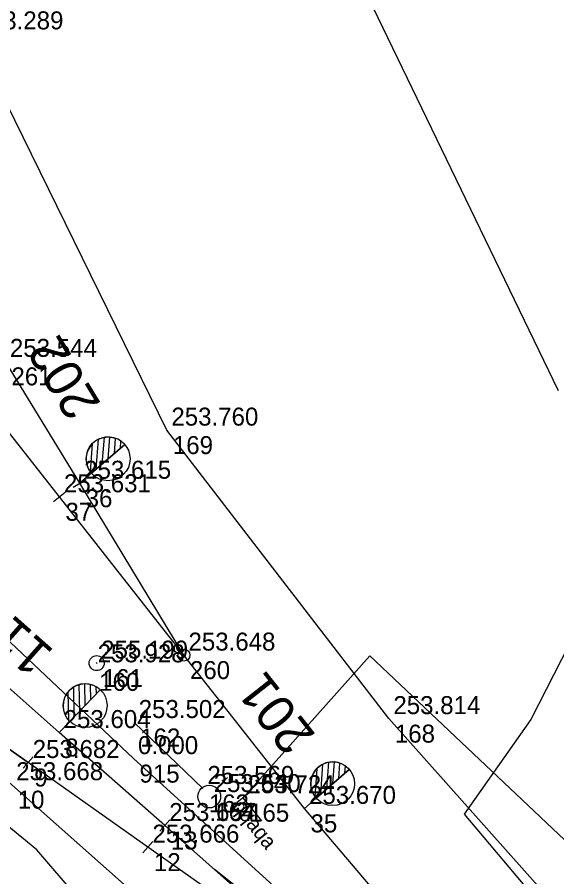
# Model space of a CAD drawing. Extents: x -496688 to -495455, y -1089309 to -1088026.
# Drawn here: x -495862.8 to -495826.8, y -1088721 to -1088663.7 of the extents above; entities that cross this region are included whole.
import ezdxf

# ---------------------------------------------------------------- set-up
doc = ezdxf.new("R2010")
doc.units = 0
for name, color, linetype in [('Vrstva 1', 7, 'Continuous'), ('Vrstva 2', 7, 'Continuous'), ('Vrstva 25', 7, 'Continuous'), ('Vrstva 36', 7, 'Continuous'), ('Vrstva 49', 7, 'Continuous'), ('Vrstva 53', 7, 'Continuous'), ('Vrstva 55', 7, 'Continuous'), ('Vrstva 6', 7, 'Continuous'), ('Vrstva 60', 7, 'Continuous'), ('Vrstva 61', 7, 'Continuous')]:
    doc.layers.add(name, color=color, linetype=linetype)

msp = doc.modelspace()

# ---------------------------------------------------------------- linework, layer by layer
at = {"layer": 'Vrstva 1'}
for points in [[(-495794.281, -1088769.662), (-495806.718, -1088758.644), (-495819.114, -1088747.662), (-495828.107, -1088739.648), (-495840.608, -1088728.579), (-495852.984, -1088717.621), (-495860.029, -1088711.42), (-495872.461, -1088700.397), (-495884.955, -1088689.319), (-495893.533, -1088681.721), (-495913.179, -1088664.263), (-495947.105, -1088634.191), (-495952.116, -1088629.76), (-495964.613, -1088618.686), (-495984.901, -1088600.717), (-495997.336, -1088589.715), (-496002.819, -1088584.884), (-496021.751, -1088568.167), (-496024.418, -1088565.811), (-496062.504, -1088532.205), (-496086.773, -1088510.767), (-496106.199, -1088493.629), (-496127.249, -1088474.987), (-496164.633, -1088441.927)], [(-495860.009, -1088695.696), (-495879.111, -1088671.4), (-495889.727, -1088657.952), (-495895.948, -1088650.027), (-495908.172, -1088634.454), (-495920.247, -1088619.061), (-495928.37, -1088608.7), (-495943.31, -1088589.65), (-495946.89, -1088584.98), (-495957.87, -1088569.42), (-495971.21, -1088547.86), (-495978.61, -1088535.04), (-495988.2, -1088517.33), (-495993.92, -1088506.2), (-495995.29, -1088503.47), (-496002.91, -1088487.94)], [(-495784.233, -1088784.889), (-495790.007, -1088779.778), (-495797.538, -1088773.109), (-495802.96, -1088768.305), (-495829.435, -1088744.846), (-495841.88, -1088733.81), (-495854.312, -1088722.787), (-495863.196, -1088714.897), (-495875.701, -1088703.825), (-495888.14, -1088692.81), (-495895.834, -1088685.958), (-495903.705, -1088678.98), (-495916.136, -1088667.962), (-495923.285, -1088661.656)], [(-495851.703, -1088706.254), (-495858.66, -1088694.79), (-495863.612, -1088686.663), (-495872.713, -1088671.728)], [(-495843.661, -1088716.477), (-495851.703, -1088706.254), (-495860.009, -1088695.696)], [(-495597.746, -1088928.689), (-495606.602, -1088921.27), (-495628.038, -1088903.237), (-495662.023, -1088874.554), (-495695.238, -1088846.561), (-495728.41, -1088818.593), (-495747.734, -1088802.274), (-495769.843, -1088783.642), (-495779.5, -1088775.496), (-495789.139, -1088767.364), (-495796.782, -1088760.905), (-495804.819, -1088754.113), (-495818.323, -1088744.415), (-495826.921, -1088738.229), (-495840.608, -1088728.579), (-495854.107, -1088719.062), (-495862.093, -1088713.418), (-495875.701, -1088703.825)], [(-495817.188, -1088742.979), (-495827.498, -1088733.605), (-495838.015, -1088723.129), (-495843.661, -1088716.477)]]:
    msp.add_lwpolyline(points, dxfattribs=at)
at = {"layer": 'Vrstva 2'}
for p, q in [((-495857.944, -1088694.031), (-495857.799, -1088692.138)), ((-495857.554, -1088693.846), (-495857.401, -1088691.854)), ((-495857.152, -1088693.501), (-495857.015, -1088691.73)), ((-495856.75, -1088693.154), (-495856.639, -1088691.714)), ((-495856.347, -1088692.81), (-495856.269, -1088691.798)), ((-495855.944, -1088692.464), (-495855.907, -1088691.989)), ((-495857.877, -1088694.123), (-495855.655, -1088692.217)), ((-495855.655, -1088692.217), (-495857.877, -1088694.122)), ((-495857.878, -1088694.123), (-495858.66, -1088694.79)), ((-495857.877, -1088694.122), (-495857.877, -1088694.123)), ((-495859.087, -1088695.049), (-495858.233, -1088694.531)), ((-495860.401, -1088696.005), (-495859.617, -1088695.387)), ((-495858.283, -1088709.609), (-495858.311, -1088708.166)), ((-495859.389, -1088710.596), (-495859.426, -1088708.698)), ((-495859.314, -1088710.681), (-495857.285, -1088708.571)), ((-495857.285, -1088708.571), (-495859.314, -1088710.68)), ((-495859.019, -1088710.375), (-495859.057, -1088708.377)), ((-495858.651, -1088709.993), (-495858.686, -1088708.217)), ((-495857.916, -1088709.227), (-495857.936, -1088708.212)), ((-495857.548, -1088708.845), (-495857.557, -1088708.368)), ((-495859.314, -1088710.682), (-495860.029, -1088711.42)), ((-495859.314, -1088710.68), (-495859.314, -1088710.681)), ((-495862.424, -1088713.792), (-495861.762, -1088713.044)), ((-495842.953, -1088715.712), (-495842.827, -1088713.818)), ((-495840.682, -1088713.874), (-495842.885, -1088715.801)), ((-495842.884, -1088715.802), (-495840.682, -1088713.874)), ((-495842.564, -1088715.523), (-495842.431, -1088713.528)), ((-495842.166, -1088715.173), (-495842.047, -1088713.401)), ((-495841.767, -1088714.823), (-495841.67, -1088713.383)), ((-495841.367, -1088714.474), (-495841.299, -1088713.461)), ((-495840.968, -1088714.124), (-495840.935, -1088713.649)), ((-495842.885, -1088715.802), (-495843.661, -1088716.477)), ((-495842.885, -1088715.801), (-495842.884, -1088715.802)), ((-495853.316, -1088717.995), (-495852.652, -1088717.247)), ((-495854.439, -1088719.436), (-495853.775, -1088718.688))]:
    msp.add_line(p, q, dxfattribs=at)
for points in [[(-495858.66, -1088694.79), (-495863.612, -1088686.663), (-495872.713, -1088671.728)], [(-495860.029, -1088711.42), (-495872.461, -1088700.397), (-495884.955, -1088689.319)], [(-495851.703, -1088706.254), (-495858.66, -1088694.79)], [(-495843.661, -1088716.477), (-495851.703, -1088706.254), (-495860.009, -1088695.696)], [(-495875.701, -1088703.825), (-495862.093, -1088713.418)], [(-495828.107, -1088739.648), (-495840.608, -1088728.579), (-495852.983, -1088717.62)], [(-495826.921, -1088738.229), (-495840.608, -1088728.579), (-495854.107, -1088719.062)], [(-495830.797, -1088735.496), (-495849.674, -1088720.551)]]:
    msp.add_lwpolyline(points, dxfattribs=at)
for centre, radius in [((-495856.761, -1088693.163), 1.462), ((-495851.703, -1088706.254), 0.4), ((-495858.294, -1088709.619), 1.462), ((-495841.778, -1088714.832), 1.462)]:
    msp.add_circle(centre, radius, dxfattribs=at)
for centre, start, end in [((-495856.766, -1088693.17), 40.62641, 220.58726), ((-495858.299, -1088709.626), 46.11677, 226.07762), ((-495841.783, -1088714.838), 41.1877, 221.14855)]:
    msp.add_arc(centre, 1.464, start, end, dxfattribs=at)
at = {"layer": 'Vrstva 25'}
msp.add_line((-495857.489, -1088706.822), (-495857.563, -1088706.756), dxfattribs=at)
msp.add_circle((-495857.526, -1088706.789), 0.5, dxfattribs=at)
at = {"layer": 'Vrstva 36'}
msp.add_line((-495849.493, -1088715.144), (-495848.802, -1088714.421), dxfattribs=at)
msp.add_lwpolyline([(-495850.441, -1088715.147), (-495855.024, -1088710.75)], dxfattribs=at)
msp.add_circle((-495850.017, -1088715.689), 0.757, dxfattribs=at)
at = {"layer": 'Vrstva 49'}
msp.add_lwpolyline([(-495763.13, -1088778.611), (-495765.306, -1088777.077), (-495791.441, -1088755.289), (-495814.323, -1088737.085), (-495838.033, -1088710.491), (-495852.843, -1088691.248), (-495865.843, -1088664.821), (-495876.068, -1088642.052), (-495881.546, -1088626.667), (-495882.811, -1088621.688)], dxfattribs=at)
at = {"layer": 'Vrstva 53'}
for p, q in [((-495859.86, -1088620.14), (-495826.74, -1088688.6)), ((-495825.16, -1088703.86), (-495828.57, -1088710.55)), ((-495828.57, -1088710.55), (-495833.01, -1088716.87)), ((-495833.01, -1088716.87), (-495825.11, -1088726.21))]:
    msp.add_line(p, q, dxfattribs=at)
at = {"layer": 'Vrstva 55'}
for p, q in [((-495861.51, -1088719.25), (-495872.18, -1088710.53)), ((-495820.95, -1088766.37), (-495861.51, -1088719.25))]:
    msp.add_line(p, q, dxfattribs=at)
msp.add_lwpolyline([(-495876.99, -1088692.49), (-495855.07, -1088713.16), (-495793.54, -1088769.11), (-495671.98, -1088874.82), (-495634.71, -1088905.31), (-495611.24, -1088924.48), (-495609.02, -1088926.3), (-495602.5, -1088931.63)], dxfattribs=at)
at = {"layer": 'Vrstva 6'}
for p, q in [((-495847.758, -1088715.765), (-495839.294, -1088706.307)), ((-495839.294, -1088706.307), (-495815.484, -1088728.83)), ((-495847.368, -1088715.452), (-495848.148, -1088716.078)), ((-495846.519, -1088717.311), (-495847.758, -1088715.765))]:
    msp.add_line(p, q, dxfattribs=at)
at = {"layer": 'Vrstva 60'}
for p, q in [((-495852.843, -1088691.248), (-495852.843, -1088691.248)), ((-495852.843, -1088691.248), (-495852.843, -1088691.248)), ((-495858.66, -1088694.79), (-495858.66, -1088694.79)), ((-495858.66, -1088694.79), (-495858.66, -1088694.79)), ((-495860.009, -1088695.696), (-495860.009, -1088695.696)), ((-495860.009, -1088695.696), (-495860.009, -1088695.696)), ((-495851.703, -1088706.254), (-495851.703, -1088706.254)), ((-495851.703, -1088706.254), (-495851.703, -1088706.254)), ((-495857.759, -1088707.036), (-495857.759, -1088707.036)), ((-495857.759, -1088707.036), (-495857.759, -1088707.036)), ((-495857.526, -1088706.789), (-495857.526, -1088706.789)), ((-495857.526, -1088706.789), (-495857.526, -1088706.789)), ((-495855.024, -1088710.75), (-495855.024, -1088710.75)), ((-495855.024, -1088710.75), (-495855.024, -1088710.75)), ((-495838.033, -1088710.491), (-495838.033, -1088710.491)), ((-495838.033, -1088710.491), (-495838.033, -1088710.491)), ((-495860.029, -1088711.42), (-495860.029, -1088711.42)), ((-495860.029, -1088711.42), (-495860.029, -1088711.42)), ((-495855.07, -1088713.16), (-495855.07, -1088713.16)), ((-495855.07, -1088713.16), (-495855.07, -1088713.16)), ((-495862.093, -1088713.418), (-495862.093, -1088713.418)), ((-495862.093, -1088713.418), (-495862.093, -1088713.418)), ((-495850.441, -1088715.147), (-495850.441, -1088715.147)), ((-495850.441, -1088715.147), (-495850.441, -1088715.147)), ((-495850.017, -1088715.69), (-495850.017, -1088715.69)), ((-495850.017, -1088715.69), (-495850.017, -1088715.69)), ((-495847.758, -1088715.765), (-495847.758, -1088715.765)), ((-495847.758, -1088715.765), (-495847.758, -1088715.765)), ((-495843.661, -1088716.477), (-495843.661, -1088716.477)), ((-495843.661, -1088716.477), (-495843.661, -1088716.477)), ((-495852.984, -1088717.621), (-495852.984, -1088717.621)), ((-495852.984, -1088717.621), (-495852.984, -1088717.621)), ((-495854.107, -1088719.062), (-495854.107, -1088719.062)), ((-495854.107, -1088719.062), (-495854.107, -1088719.062))]:
    msp.add_line(p, q, dxfattribs=at)

# ---------------------------------------------------------------- texts
at = {"layer": 'Vrstva 2'}
for s, rotation, p in [('202', 121.25175, (-495857.206, -1088689.502)), ('11', 138.39129, (-495860.293, -1088705.999)), ('201', 128.19063, (-495842.868, -1088711.586))]:
    msp.add_text(s, height=2.5, rotation=rotation, dxfattribs=at).set_placement(p)
at = {"layer": 'Vrstva 6'}
msp.add_text('qqaqa', height=1, rotation=308.70973, dxfattribs=at).set_placement((-495848.538, -1088716.39))
at = {"layer": 'Vrstva 60'}
for s, p in [('261', (-495863.212, -1088688.263)), ('261', (-495863.212, -1088688.263)), ('169', (-495852.443, -1088692.848)), ('169', (-495852.443, -1088692.848)), ('36', (-495858.26, -1088696.39)), ('36', (-495858.26, -1088696.39)), ('37', (-495859.609, -1088697.296)), ('37', (-495859.609, -1088697.296)), ('260', (-495851.303, -1088707.854)), ('260', (-495851.303, -1088707.854)), ('160', (-495857.359, -1088708.636)), ('160', (-495857.359, -1088708.636)), ('161', (-495857.126, -1088708.389)), ('161', (-495857.126, -1088708.389)), ('168', (-495837.633, -1088712.091)), ('168', (-495837.633, -1088712.091)), ('162', (-495854.624, -1088712.35)), ('162', (-495854.624, -1088712.35)), ('8', (-495859.629, -1088713.02)), ('8', (-495859.629, -1088713.02)), ('9', (-495861.693, -1088715.018)), ('9', (-495861.693, -1088715.018)), ('915', (-495854.67, -1088714.76)), ('915', (-495854.67, -1088714.76)), ('10', (-495862.796, -1088716.497)), ('10', (-495862.796, -1088716.497)), ('163', (-495850.041, -1088716.747)), ('163', (-495850.041, -1088716.747)), ('164', (-495849.617, -1088717.29)), ('164', (-495849.617, -1088717.29)), ('165', (-495847.358, -1088717.365)), ('165', (-495847.358, -1088717.365)), ('35', (-495843.261, -1088718.077)), ('35', (-495843.261, -1088718.077)), ('13', (-495852.584, -1088719.221)), ('13', (-495852.584, -1088719.221)), ('12', (-495853.707, -1088720.662)), ('12', (-495853.707, -1088720.662))]:
    msp.add_text(s, height=1.2, dxfattribs=at).set_placement(p)
at = {"layer": 'Vrstva 61'}
for s, p in [('253.289', (-495865.543, -1088664.521)), ('253.289', (-495865.543, -1088664.521)), ('253.544', (-495863.312, -1088686.363)), ('253.544', (-495863.312, -1088686.363)), ('253.760', (-495852.543, -1088690.948)), ('253.760', (-495852.543, -1088690.948)), ('253.615', (-495858.36, -1088694.49)), ('253.615', (-495858.36, -1088694.49)), ('253.631', (-495859.709, -1088695.396)), ('253.631', (-495859.709, -1088695.396)), ('253.648', (-495851.403, -1088705.954)), ('253.648', (-495851.403, -1088705.954)), ('255.199', (-495857.226, -1088706.489)), ('255.199', (-495857.226, -1088706.489)), ('253.928', (-495857.459, -1088706.736)), ('253.928', (-495857.459, -1088706.736)), ('253.502', (-495854.724, -1088710.45)), ('253.502', (-495854.724, -1088710.45)), ('253.814', (-495837.733, -1088710.191)), ('253.814', (-495837.733, -1088710.191)), ('253.604', (-495859.729, -1088711.12)), ('253.604', (-495859.729, -1088711.12)), ('253.682', (-495861.793, -1088713.118)), ('253.682', (-495861.793, -1088713.118)), ('0.000', (-495854.77, -1088712.86)), ('0.000', (-495854.77, -1088712.86)), ('253.668', (-495862.896, -1088714.597)), ('253.668', (-495862.896, -1088714.597)), ('253.569', (-495850.141, -1088714.847)), ('253.569', (-495850.141, -1088714.847)), ('253.640', (-495849.717, -1088715.39)), ('253.640', (-495849.717, -1088715.39)), ('253.724', (-495847.458, -1088715.465)), ('253.724', (-495847.458, -1088715.465)), ('253.670', (-495843.361, -1088716.177)), ('253.670', (-495843.361, -1088716.177)), ('253.657', (-495852.684, -1088717.321)), ('253.657', (-495852.684, -1088717.321)), ('253.666', (-495853.807, -1088718.762)), ('253.666', (-495853.807, -1088718.762))]:
    msp.add_text(s, height=1.2, dxfattribs=at).set_placement(p)

doc.saveas('drawing.dxf')
